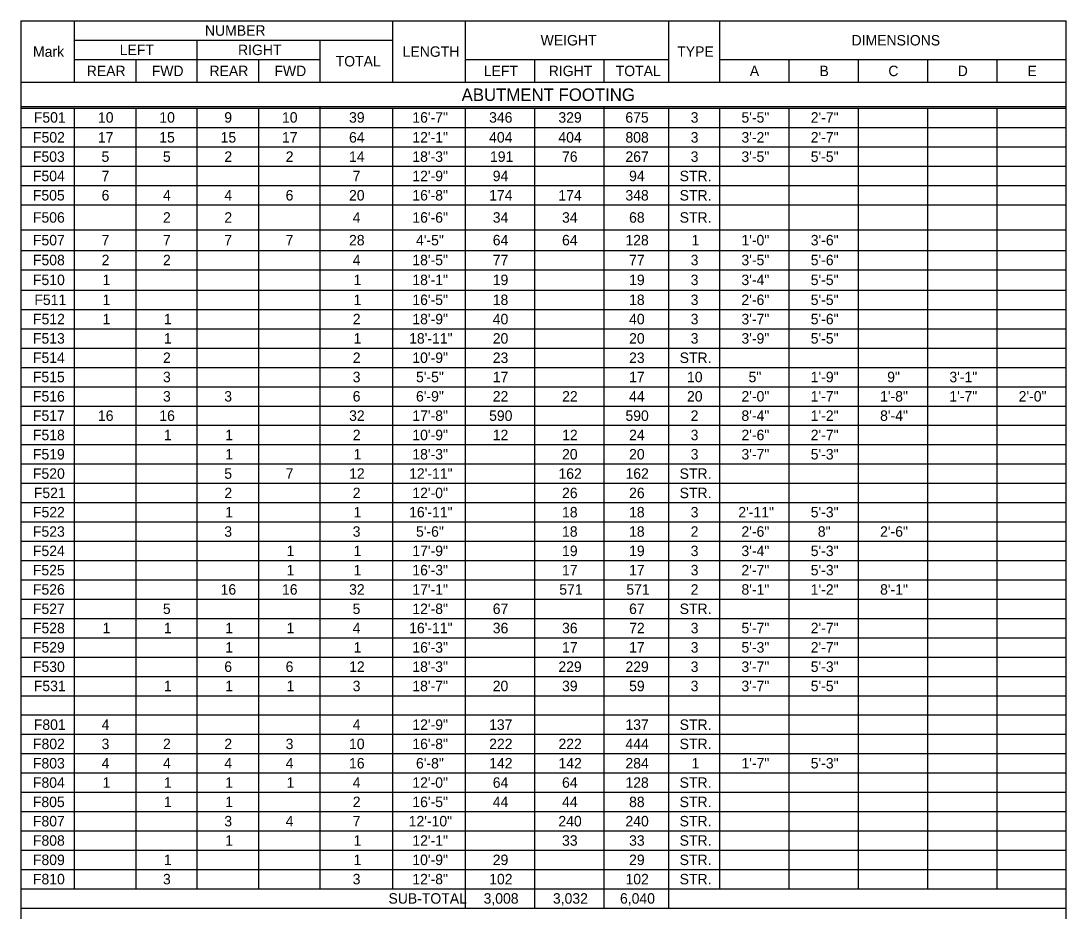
# Model space of a CAD drawing. Extents: x -18.5 to 33.3, y 0.6 to 37.5.
# Drawn here: x 1.71 to 15.71, y 8.69 to 20.61 of the extents above; entities that cross this region are included whole.
import ezdxf

# ---------------------------------------------------------------- set-up
doc = ezdxf.new("R2010")
doc.units = 0
doc.layers.add('BR_X_Beam_Centerline', color=7, linetype='Continuous')
doc.layers.add('Default', color=7, linetype='Continuous')

msp = doc.modelspace()

# ---------------------------------------------------------------- linework, layer by layer
at = {"layer": 'Default'}
for p, q in [((1.715, 20.614), (15.714, 20.614)), ((1.715, 20.614), (1.715, 19.447)), ((2.43, 20.614), (2.43, 19.792)), ((6.691, 20.614), (6.691, 19.792)), ((7.665, 20.614), (7.665, 19.792)), ((10.388, 20.614), (10.388, 19.792)), ((11.073, 20.614), (11.073, 19.792)), ((15.714, 1.913), (15.714, 20.614)), ((2.43, 20.355), (6.691, 20.355)), ((4.073, 20.355), (4.073, 19.792)), ((5.717, 20.355), (5.717, 19.792)), ((2.43, 20.097), (5.717, 20.097)), ((3.252, 20.097), (3.252, 19.792)), ((4.895, 20.097), (4.895, 19.792)), ((7.665, 20.097), (10.388, 20.097)), ((8.593, 20.097), (8.593, 19.792)), ((9.521, 20.097), (9.521, 19.792)), ((11.073, 20.097), (15.714, 20.097)), ((12.001, 20.097), (12.001, 19.792)), ((12.93, 20.097), (12.93, 19.792)), ((13.858, 20.097), (13.858, 19.792)), ((14.786, 20.097), (14.786, 19.792)), ((1.715, 19.792), (15.714, 19.792)), ((1.715, 19.468), (15.714, 19.468)), ((1.715, 19.468), (1.715, 8.385)), ((5.717, 19.468), (5.717, 8.988)), ((9.521, 19.468), (9.521, 8.73)), ((1.715, 19.447), (15.714, 19.447)), ((2.43, 19.447), (2.43, 8.988)), ((3.252, 19.447), (3.252, 8.988)), ((4.073, 19.447), (4.073, 8.988)), ((4.895, 19.447), (4.895, 8.988)), ((6.691, 19.447), (6.691, 8.988)), ((7.665, 19.447), (7.665, 8.73)), ((8.593, 19.447), (8.593, 8.73)), ((10.388, 19.447), (10.388, 8.73)), ((11.073, 19.447), (11.073, 8.988)), ((12.001, 19.447), (12.001, 8.988)), ((12.93, 19.447), (12.93, 8.988)), ((13.858, 19.447), (13.858, 8.988)), ((14.786, 19.447), (14.786, 8.988)), ((1.715, 19.184), (15.714, 19.184)), ((1.715, 18.925), (15.714, 18.925)), ((1.715, 18.666), (15.714, 18.666)), ((1.715, 18.408), (15.714, 18.408)), ((1.715, 18.149), (15.714, 18.149)), ((1.715, 17.814), (15.714, 17.814)), ((1.715, 17.54), (15.714, 17.54)), ((1.715, 17.281), (15.714, 17.281)), ((1.715, 17.008), (15.714, 17.008)), ((1.715, 16.749), (15.714, 16.749)), ((1.715, 16.49), (15.714, 16.49)), ((1.715, 16.232), (15.714, 16.232)), ((1.715, 15.973), (15.714, 15.973)), ((1.715, 15.714), (15.714, 15.714)), ((1.715, 15.455), (15.714, 15.455)), ((1.715, 15.197), (15.714, 15.197)), ((1.715, 14.938), (15.714, 14.938)), ((1.715, 14.679), (15.714, 14.679)), ((1.715, 14.421), (15.714, 14.421)), ((1.715, 14.162), (15.714, 14.162)), ((1.715, 13.903), (15.714, 13.903)), ((1.715, 13.645), (15.714, 13.645)), ((1.715, 13.386), (15.714, 13.386)), ((1.715, 13.127), (15.714, 13.127)), ((1.715, 12.869), (15.714, 12.869)), ((1.715, 12.61), (15.714, 12.61)), ((1.715, 12.351), (15.714, 12.351)), ((1.715, 12.093), (15.714, 12.093)), ((1.715, 11.834), (15.714, 11.834)), ((1.715, 11.575), (15.714, 11.575)), ((1.715, 11.317), (15.714, 11.317)), ((1.715, 11.058), (15.714, 11.058)), ((1.715, 10.799), (15.714, 10.799)), ((1.715, 10.54), (15.714, 10.54)), ((1.715, 10.282), (15.714, 10.282)), ((1.715, 10.023), (15.714, 10.023)), ((1.715, 9.764), (15.714, 9.764)), ((1.715, 9.506), (15.714, 9.506)), ((1.715, 9.247), (15.714, 9.247)), ((1.715, 8.988), (15.714, 8.988)), ((1.715, 8.73), (15.714, 8.73))]:
    msp.add_line(p, q, dxfattribs=at)

# ---------------------------------------------------------------- texts
at = {"layer": 'BR_X_Beam_Centerline'}
for s, height, p in [('NUMBER', 0.14, (4.18, 20.415)), ('WEIGHT', 0.14, (8.676, 20.285)), ('DIMENSIONS', 0.14, (12.841, 20.285)), ('Mark', 0.14, (1.877, 20.133)), ('LEFT', 0.14, (3.038, 20.156)), ('RIGHT', 0.14, (4.623, 20.156)), ('LENGTH', 0.14, (6.828, 20.133)), ('TYPE', 0.14, (10.506, 20.133)), ('TOTAL', 0.14, (5.931, 20.004)), ('REAR', 0.14, (2.597, 19.874)), ('FWD', 0.14, (3.467, 19.874)), ('REAR', 0.14, (4.241, 19.874)), ('FWD', 0.14, (5.11, 19.874)), ('LEFT', 0.14, (7.915, 19.874)), ('RIGHT', 0.14, (8.785, 19.874)), ('TOTAL', 0.14, (9.682, 19.874)), ('A', 0.14, (11.478, 19.874)), ('B', 0.14, (12.411, 19.874)), ('C', 0.14, (13.334, 19.874)), ('D', 0.14, (14.263, 19.874)), ('E', 0.14, (15.196, 19.874)), ('ABUTMENT FOOTING', 0.16799, (7.618, 19.541)), ('F501', 0.14, (1.888, 19.251)), ('10', 0.14, (2.747, 19.251)), ('10', 0.14, (3.569, 19.251)), ('9', 0.14, (4.439, 19.251)), ('10', 0.14, (5.212, 19.251)), ('39', 0.14, (6.11, 19.251)), ('16\'-7"', 0.14, (6.958, 19.251)), ('346', 0.14, (7.986, 19.251)), ('329', 0.14, (8.914, 19.251)), ('675', 0.14, (9.811, 19.251)), ('3', 0.14, (10.686, 19.251)), ('5\'-5"', 0.14, (11.366, 19.251)), ('2\'-7"', 0.14, (12.294, 19.251)), ('F502', 0.14, (1.877, 18.984)), ('17', 0.14, (2.747, 18.984)), ('15', 0.14, (3.568, 18.984)), ('15', 0.14, (4.39, 18.984)), ('17', 0.14, (5.212, 18.984)), ('64', 0.14, (6.11, 18.984)), ('12\'-1"', 0.14, (6.958, 18.984)), ('404', 0.14, (7.986, 18.984)), ('404', 0.14, (8.914, 18.984)), ('808', 0.14, (9.812, 18.984)), ('3', 0.14, (10.686, 18.984)), ('3\'-2"', 0.14, (11.366, 18.984)), ('2\'-7"', 0.14, (12.294, 18.984)), ('F503', 0.14, (1.876, 18.726)), ('5', 0.14, (2.795, 18.726)), ('5', 0.14, (3.617, 18.726)), ('2', 0.14, (4.44, 18.726)), ('2', 0.14, (5.262, 18.726)), ('14', 0.14, (6.11, 18.726)), ('18\'-3"', 0.14, (6.958, 18.726)), ('191', 0.14, (7.998, 18.726)), ('76', 0.14, (8.963, 18.726)), ('267', 0.14, (9.812, 18.726)), ('3', 0.14, (10.686, 18.726)), ('3\'-5"', 0.14, (11.366, 18.726)), ('5\'-5"', 0.14, (12.294, 18.726)), ('F504', 0.14, (1.876, 18.467)), ('7', 0.14, (2.796, 18.467)), ('7', 0.14, (6.159, 18.467)), ('12\'-9"', 0.14, (6.958, 18.467)), ('94', 0.14, (8.035, 18.467)), ('94', 0.14, (9.861, 18.467)), ('STR.', 0.14, (10.538, 18.467)), ('F505', 0.14, (1.875, 18.208)), ('6', 0.14, (2.796, 18.208)), ('4', 0.14, (3.618, 18.208)), ('4', 0.14, (4.44, 18.208)), ('6', 0.14, (5.261, 18.208)), ('20', 0.14, (6.11, 18.208)), ('16\'-8"', 0.14, (6.958, 18.208)), ('174', 0.14, (7.986, 18.208)), ('174', 0.14, (8.914, 18.208)), ('348', 0.14, (9.812, 18.208)), ('STR.', 0.14, (10.538, 18.208)), ('F506', 0.14, (1.876, 17.911)), ('2', 0.14, (3.618, 17.911)), ('2', 0.14, (4.44, 17.911)), ('4', 0.14, (6.159, 17.911)), ('16\'-6"', 0.14, (6.958, 17.911)), ('34', 0.14, (8.035, 17.911)), ('34', 0.14, (8.963, 17.911)), ('68', 0.14, (9.861, 17.911)), ('STR.', 0.14, (10.538, 17.911)), ('F507', 0.14, (1.876, 17.607)), ('7', 0.14, (2.796, 17.607)), ('7', 0.14, (3.618, 17.607)), ('7', 0.14, (4.439, 17.607)), ('7', 0.14, (5.261, 17.607)), ('28', 0.14, (6.11, 17.607)), ('4\'-5"', 0.14, (7.007, 17.607)), ('64', 0.14, (8.035, 17.607)), ('64', 0.14, (8.963, 17.607)), ('128', 0.14, (9.812, 17.607)), ('1', 0.14, (10.698, 17.607)), ('1\'-0"', 0.14, (11.366, 17.607)), ('3\'-6"', 0.14, (12.294, 17.607)), ('F508', 0.14, (1.876, 17.341)), ('2', 0.14, (2.797, 17.341)), ('2', 0.14, (3.618, 17.341)), ('4', 0.14, (6.159, 17.341)), ('18\'-5"', 0.14, (6.958, 17.341)), ('77', 0.14, (8.035, 17.341)), ('77', 0.14, (9.861, 17.341)), ('3', 0.14, (10.686, 17.341)), ('3\'-5"', 0.14, (11.366, 17.341)), ('5\'-6"', 0.14, (12.294, 17.341)), ('F510', 0.14, (1.876, 17.075)), ('1', 0.14, (2.808, 17.075)), ('1', 0.14, (6.171, 17.075)), ('18\'-1"', 0.14, (6.958, 17.075)), ('19', 0.14, (8.035, 17.075)), ('19', 0.14, (9.861, 17.075)), ('3', 0.14, (10.686, 17.075)), ('3\'-4"', 0.14, (11.366, 17.075)), ('5\'-5"', 0.14, (12.294, 17.075)), ('F511', 0.14, (1.895, 16.808)), ('1', 0.14, (2.808, 16.808)), ('1', 0.14, (6.171, 16.808)), ('16\'-5"', 0.14, (6.958, 16.808)), ('18', 0.14, (8.035, 16.808)), ('18', 0.14, (9.861, 16.808)), ('3', 0.14, (10.686, 16.808)), ('2\'-6"', 0.14, (11.366, 16.808)), ('5\'-5"', 0.14, (12.294, 16.808)), ('F512', 0.14, (1.877, 16.55)), ('1', 0.14, (2.808, 16.55)), ('1', 0.14, (3.63, 16.55)), ('2', 0.14, (6.16, 16.55)), ('18\'-9"', 0.14, (6.958, 16.55)), ('40', 0.14, (8.035, 16.55)), ('40', 0.14, (9.861, 16.55)), ('3', 0.14, (10.686, 16.55)), ('3\'-7"', 0.14, (11.366, 16.55)), ('5\'-6"', 0.14, (12.294, 16.55)), ('F513', 0.14, (1.876, 16.291)), ('1', 0.14, (3.63, 16.291)), ('1', 0.14, (6.171, 16.291)), ('18\'-11"', 0.14, (6.915, 16.291)), ('20', 0.14, (8.035, 16.291)), ('20', 0.14, (9.861, 16.291)), ('3', 0.14, (10.686, 16.291)), ('3\'-9"', 0.14, (11.366, 16.291)), ('5\'-5"', 0.14, (12.294, 16.291)), ('F514', 0.14, (1.876, 16.032)), ('2', 0.14, (3.618, 16.032)), ('2', 0.14, (6.16, 16.032)), ('10\'-9"', 0.14, (6.958, 16.032)), ('23', 0.14, (8.035, 16.032)), ('23', 0.14, (9.861, 16.032)), ('STR.', 0.14, (10.538, 16.032)), ('F515', 0.14, (1.875, 15.774)), ('3', 0.14, (3.618, 15.774)), ('3', 0.14, (6.159, 15.774)), ('5\'-5"', 0.14, (7.007, 15.774)), ('17', 0.14, (8.035, 15.774)), ('17', 0.14, (9.861, 15.774)), ('10', 0.14, (10.637, 15.774)), ('5"', 0.14, (11.461, 15.774)), ('1\'-9"', 0.14, (12.294, 15.774)), ('9"', 0.14, (13.318, 15.774)), ('3\'-1"', 0.14, (14.151, 15.774)), ('F516', 0.14, (1.876, 15.515)), ('3', 0.14, (3.618, 15.515)), ('3', 0.14, (4.439, 15.515)), ('6', 0.14, (6.159, 15.515)), ('6\'-9"', 0.14, (7.007, 15.515)), ('22', 0.14, (8.035, 15.515)), ('22', 0.14, (8.964, 15.515)), ('44', 0.14, (9.861, 15.515)), ('20', 0.14, (10.637, 15.515)), ('2\'-0"', 0.14, (11.366, 15.515)), ('1\'-7"', 0.14, (12.294, 15.515)), ('1\'-8"', 0.14, (13.223, 15.515)), ('1\'-7"', 0.14, (14.151, 15.515)), ('2\'-0"', 0.14, (15.079, 15.515)), ('F517', 0.14, (1.876, 15.256)), ('16', 0.14, (2.747, 15.256)), ('16', 0.14, (3.569, 15.256)), ('32', 0.14, (6.111, 15.256)), ('17\'-8"', 0.14, (6.958, 15.256)), ('590', 0.14, (7.986, 15.256)), ('590', 0.14, (9.812, 15.256)), ('2', 0.14, (10.686, 15.256)), ('8\'-4"', 0.14, (11.366, 15.256)), ('1\'-2"', 0.14, (12.294, 15.256)), ('8\'-4"', 0.14, (13.223, 15.256)), ('F518', 0.14, (1.876, 14.997)), ('1', 0.14, (3.63, 14.997)), ('1', 0.14, (4.452, 14.997)), ('2', 0.14, (6.16, 14.997)), ('10\'-9"', 0.14, (6.958, 14.997)), ('12', 0.14, (8.035, 14.997)), ('12', 0.14, (8.964, 14.997)), ('24', 0.14, (9.861, 14.997)), ('3', 0.14, (10.686, 14.997)), ('2\'-6"', 0.14, (11.366, 14.997)), ('2\'-7"', 0.14, (12.294, 14.997)), ('F519', 0.14, (1.876, 14.739)), ('1', 0.14, (4.452, 14.739)), ('1', 0.14, (6.171, 14.739)), ('18\'-3"', 0.14, (6.958, 14.739)), ('20', 0.14, (8.963, 14.739)), ('20', 0.14, (9.861, 14.739)), ('3', 0.14, (10.686, 14.739)), ('3\'-7"', 0.14, (11.366, 14.739)), ('5\'-3"', 0.14, (12.294, 14.739)), ('F520', 0.14, (1.876, 14.48)), ('5', 0.14, (4.439, 14.48)), ('7', 0.14, (5.261, 14.48)), ('12', 0.14, (6.111, 14.48)), ('12\'-11"', 0.14, (6.915, 14.48)), ('162', 0.14, (8.915, 14.48)), ('162', 0.14, (9.813, 14.48)), ('STR.', 0.14, (10.538, 14.48)), ('F521', 0.14, (1.888, 14.221)), ('2', 0.14, (4.44, 14.221)), ('2', 0.14, (6.16, 14.221)), ('12\'-0"', 0.14, (6.958, 14.221)), ('26', 0.14, (8.963, 14.221)), ('26', 0.14, (9.861, 14.221)), ('STR.', 0.14, (10.538, 14.221)), ('F522', 0.14, (1.877, 13.963)), ('1', 0.14, (4.452, 13.963)), ('1', 0.14, (6.171, 13.963)), ('16\'-11"', 0.14, (6.915, 13.963)), ('18', 0.14, (8.963, 13.963)), ('18', 0.14, (9.861, 13.963)), ('3', 0.14, (10.686, 13.963)), ('2\'-11"', 0.14, (11.324, 13.963)), ('5\'-3"', 0.14, (12.294, 13.963)), ('F523', 0.14, (1.876, 13.704)), ('3', 0.14, (4.439, 13.704)), ('3', 0.14, (6.159, 13.704)), ('5\'-6"', 0.14, (7.007, 13.704)), ('18', 0.14, (8.963, 13.704)), ('18', 0.14, (9.861, 13.704)), ('2', 0.14, (10.686, 13.704)), ('2\'-6"', 0.14, (11.366, 13.704)), ('8"', 0.14, (12.389, 13.704)), ('2\'-6"', 0.14, (13.223, 13.704)), ('F524', 0.14, (1.876, 13.445)), ('1', 0.14, (5.273, 13.445)), ('1', 0.14, (6.171, 13.445)), ('17\'-9"', 0.14, (6.958, 13.445)), ('19', 0.14, (8.963, 13.445)), ('19', 0.14, (9.861, 13.445)), ('3', 0.14, (10.686, 13.445)), ('3\'-4"', 0.14, (11.366, 13.445)), ('5\'-3"', 0.14, (12.294, 13.445)), ('F525', 0.14, (1.875, 13.187)), ('1', 0.14, (5.273, 13.187)), ('1', 0.14, (6.171, 13.187)), ('16\'-3"', 0.14, (6.958, 13.187)), ('17', 0.14, (8.963, 13.187)), ('17', 0.14, (9.861, 13.187)), ('3', 0.14, (10.686, 13.187)), ('2\'-7"', 0.14, (11.366, 13.187)), ('5\'-3"', 0.14, (12.294, 13.187)), ('F526', 0.14, (1.876, 12.928)), ('16', 0.14, (4.39, 12.928)), ('16', 0.14, (5.212, 12.928)), ('32', 0.14, (6.111, 12.928)), ('17\'-1"', 0.14, (6.958, 12.928)), ('571', 0.14, (8.926, 12.928)), ('571', 0.14, (9.824, 12.928)), ('2', 0.14, (10.686, 12.928)), ('8\'-1"', 0.14, (11.366, 12.928)), ('1\'-2"', 0.14, (12.294, 12.928)), ('8\'-1"', 0.14, (13.223, 12.928)), ('F527', 0.14, (1.876, 12.669)), ('5', 0.14, (3.617, 12.669)), ('5', 0.14, (6.158, 12.669)), ('12\'-8"', 0.14, (6.958, 12.669)), ('67', 0.14, (8.035, 12.669)), ('67', 0.14, (9.861, 12.669)), ('STR.', 0.14, (10.538, 12.669)), ('F528', 0.14, (1.876, 12.411)), ('1', 0.14, (2.808, 12.411)), ('1', 0.14, (3.63, 12.411)), ('1', 0.14, (4.452, 12.411)), ('1', 0.14, (5.273, 12.411)), ('4', 0.14, (6.159, 12.411)), ('16\'-11"', 0.14, (6.915, 12.411)), ('36', 0.14, (8.035, 12.411)), ('36', 0.14, (8.963, 12.411)), ('72', 0.14, (9.862, 12.411)), ('3', 0.14, (10.686, 12.411)), ('5\'-7"', 0.14, (11.366, 12.411)), ('2\'-7"', 0.14, (12.294, 12.411)), ('F529', 0.14, (1.876, 12.152)), ('1', 0.14, (4.452, 12.152)), ('1', 0.14, (6.171, 12.152)), ('16\'-3"', 0.14, (6.958, 12.152)), ('17', 0.14, (8.963, 12.152)), ('17', 0.14, (9.861, 12.152)), ('3', 0.14, (10.686, 12.152)), ('5\'-3"', 0.14, (11.366, 12.152)), ('2\'-7"', 0.14, (12.294, 12.152)), ('F530', 0.14, (1.876, 11.893)), ('6', 0.14, (4.439, 11.893)), ('6', 0.14, (5.261, 11.893)), ('12', 0.14, (6.111, 11.893)), ('18\'-3"', 0.14, (6.958, 11.893)), ('229', 0.14, (8.914, 11.893)), ('229', 0.14, (9.812, 11.893)), ('3', 0.14, (10.686, 11.893)), ('3\'-7"', 0.14, (11.366, 11.893)), ('5\'-3"', 0.14, (12.294, 11.893)), ('F531', 0.14, (1.888, 11.635)), ('1', 0.14, (3.63, 11.635)), ('1', 0.14, (4.452, 11.635)), ('1', 0.14, (5.273, 11.635)), ('3', 0.14, (6.159, 11.635)), ('18\'-7"', 0.14, (6.958, 11.635)), ('20', 0.14, (8.035, 11.635)), ('39', 0.14, (8.963, 11.635)), ('59', 0.14, (9.861, 11.635)), ('3', 0.14, (10.686, 11.635)), ('3\'-7"', 0.14, (11.366, 11.635)), ('5\'-5"', 0.14, (12.294, 11.635)), ('F801', 0.14, (1.888, 11.117)), ('4', 0.14, (2.796, 11.117)), ('4', 0.14, (6.159, 11.117)), ('12\'-9"', 0.14, (6.958, 11.117)), ('137', 0.14, (7.986, 11.117)), ('137', 0.14, (9.812, 11.117)), ('STR.', 0.14, (10.538, 11.117)), ('F802', 0.14, (1.877, 10.859)), ('3', 0.14, (2.796, 10.859)), ('2', 0.14, (3.618, 10.859)), ('2', 0.14, (4.44, 10.859)), ('3', 0.14, (5.261, 10.859)), ('10', 0.14, (6.11, 10.859)), ('16\'-8"', 0.14, (6.958, 10.859)), ('222', 0.14, (7.987, 10.859)), ('222', 0.14, (8.915, 10.859)), ('444', 0.14, (9.812, 10.859)), ('STR.', 0.14, (10.538, 10.859)), ('F803', 0.14, (1.876, 10.6)), ('4', 0.14, (2.796, 10.6)), ('4', 0.14, (3.618, 10.6)), ('4', 0.14, (4.44, 10.6)), ('4', 0.14, (5.261, 10.6)), ('16', 0.14, (6.11, 10.6)), ('6\'-8"', 0.14, (7.007, 10.6)), ('142', 0.14, (7.987, 10.6)), ('142', 0.14, (8.915, 10.6)), ('284', 0.14, (9.812, 10.6)), ('1', 0.14, (10.698, 10.6)), ('1\'-7"', 0.14, (11.366, 10.6)), ('5\'-3"', 0.14, (12.294, 10.6)), ('F804', 0.14, (1.876, 10.341)), ('1', 0.14, (2.808, 10.341)), ('1', 0.14, (3.63, 10.341)), ('1', 0.14, (4.452, 10.341)), ('1', 0.14, (5.273, 10.341)), ('4', 0.14, (6.159, 10.341)), ('12\'-0"', 0.14, (6.958, 10.341)), ('64', 0.14, (8.035, 10.341)), ('64', 0.14, (8.963, 10.341)), ('128', 0.14, (9.812, 10.341)), ('STR.', 0.14, (10.538, 10.341)), ('F805', 0.14, (1.875, 10.082)), ('1', 0.14, (3.63, 10.082)), ('1', 0.14, (4.452, 10.082)), ('2', 0.14, (6.16, 10.082)), ('16\'-5"', 0.14, (6.958, 10.082)), ('44', 0.14, (8.035, 10.082)), ('44', 0.14, (8.963, 10.082)), ('88', 0.14, (9.861, 10.082)), ('STR.', 0.14, (10.538, 10.082)), ('F807', 0.14, (1.876, 9.824)), ('3', 0.14, (4.439, 9.824)), ('4', 0.14, (5.261, 9.824)), ('7', 0.14, (6.159, 9.824)), ('12\'-10"', 0.14, (6.909, 9.824)), ('240', 0.14, (8.914, 9.824)), ('240', 0.14, (9.812, 9.824)), ('STR.', 0.14, (10.538, 9.824)), ('F808', 0.14, (1.876, 9.565)), ('1', 0.14, (4.452, 9.565)), ('1', 0.14, (6.171, 9.565)), ('12\'-1"', 0.14, (6.958, 9.565)), ('33', 0.14, (8.963, 9.565)), ('33', 0.14, (9.861, 9.565)), ('STR.', 0.14, (10.538, 9.565)), ('F809', 0.14, (1.876, 9.306)), ('1', 0.14, (3.63, 9.306)), ('1', 0.14, (6.171, 9.306)), ('10\'-9"', 0.14, (6.958, 9.306)), ('29', 0.14, (8.035, 9.306)), ('29', 0.14, (9.861, 9.306)), ('STR.', 0.14, (10.538, 9.306)), ('F810', 0.14, (1.876, 9.048)), ('3', 0.14, (3.618, 9.048)), ('3', 0.14, (6.159, 9.048)), ('12\'-8"', 0.14, (6.958, 9.048)), ('102', 0.14, (7.987, 9.048)), ('102', 0.14, (9.813, 9.048)), ('STR.', 0.14, (10.538, 9.048)), ('SUB-TOTAL', 0.14, (6.638, 8.789)), ('3,008', 0.14, (7.912, 8.789)), ('3,032', 0.14, (8.841, 8.789)), ('6,040', 0.14, (9.739, 8.789))]:
    msp.add_text(s, height=height, dxfattribs=at).set_placement(p)

doc.saveas('drawing.dxf')
